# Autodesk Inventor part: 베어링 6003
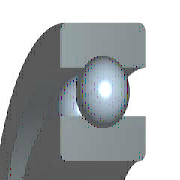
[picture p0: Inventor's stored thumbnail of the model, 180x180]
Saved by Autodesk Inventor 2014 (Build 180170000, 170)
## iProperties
Created: 2012-02
Part Number: 베어링 6003
Material: 강철, 연강
Description: 깊은 그루브 볼 베어링
Document SubType Name: Modeling
Standard: KS B 2023
Designer: mduedu
Standards Organization: KS
Language: ko-KR
Size Designation: 6003 - 17 x 35 x 10
Categories: <MemberInstance><Categories><Category DisplayName="샤프트 부품" InternalName="7f7aeb1f-a693-4053-b835-cee3144e0d98" Mnemonic="SHFT"><Category DisplayName="베어링" Inter
Density: 7.86 g/cm^3
Mass: 39.0276 g
Surface Area: 48.7538 cm^2
Volume: 4.96535 cm^3
Appearance: 노란색
IsCustomPart: 1
Author: mduedu
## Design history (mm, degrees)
sketch "스케치" dims "d0" = 4.68 (= -0.26 x WD + 0.26 x BD)
  geometry: L1 (2.66, 13)-(7.34, 13); L2 (5, 13)-(5, 10.66); L3 (5, 13)-(5, 15.34); L4 (3.261, 11.434)-(0, 11.434); L5 (0, 8.5)-(10, 8.5); L6 (3.261, 14.566)-(0, 14.566); L7 (0, 17.5)-(10, 17.5); L8 (10, 8.5)-(10, 11.434); L9 (6.739, 11.434)-(10, 11.434); L10 (6.739, 14.566)-(10, 14.566); L11 (10, 17.5)-(10, 14.566); L12 (-1.4, 0)-(8.4, 0) reference; L13 (0, -0.3)-(0, 5.3) reference
  constraints: 22 end point, 4 point on line, 2 collinear, 2 perpendicular, 2 symmetric about line, 1 midpoint, 1 parallel, 14 other
  dimensions: "d9" = 17 diameter of L5 L12 (= WD); "d11" = 35 diameter of L7 L12 (= BD); "d12" = 10 distance between parallel lines of L8 L13 (= KB); "d13" = 22.868 diameter of L9 L12 (= 0.326 x BD + 0.674 x WD)
revolve "본체" stored, may be unused: angle "d6" = 90 deg
revolve "볼" stored, may be unused: angle "d7" = 90 deg
pattern_circular "IDS_ARRAYBALL[SIMPL:T]" dims angle "d3" = 360 deg
body "Solid1"
fillet "모깎기1" dims "d1" = 0.3 (= KRS)
other parameters: "WD" = 17 [user parameter; used in 5 equation terms], "BD" = 35 [user parameter; used in 5 equation terms], "KB" = 10 [user parameter; used in 1 equation term], "KRS" = 0.3 [user parameter; used in 1 equation term], "d4" = 0, "d5" = 0, "d8" = 0, "d14" = 0, "d15" = 0, "BBA" = 0 [user parameter], "BC0" = 3250000 [user parameter], "BC" = 6050000 [user parameter], "BR" = 17.5 (= 0.5 x BD) [user parameter], "WR" = 8.5 (= 0.5 x WD) [user parameter]
